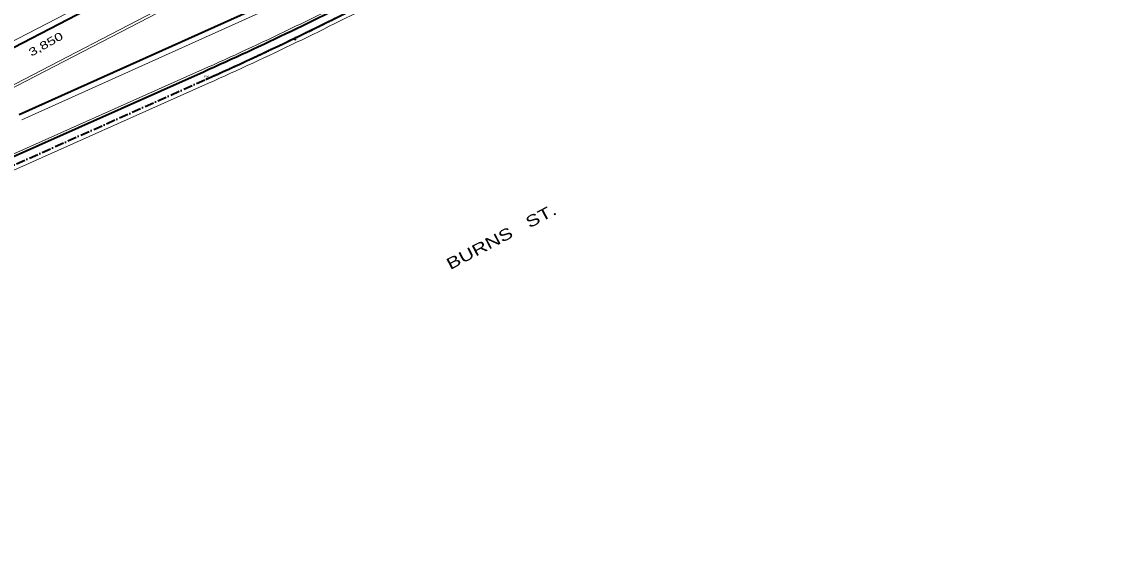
# Model space of a CAD drawing. Extents: x 2354993 to 2372084, y 6966390 to 6990057.
# Drawn here: x 2359644 to 2361546, y 6975784 to 6976700 of the extents above; entities that cross this region are included whole.
import ezdxf
from ezdxf.enums import TextEntityAlignment as Align

# ---------------------------------------------------------------- set-up
doc = ezdxf.new("R2010")
doc.units = 0
doc.header["$LTSCALE"] = 3.2
doc.linetypes.add('DOT_DASHED', pattern=[7.7, 5, -1.2, 0.3, -1.2])
for name, color, linetype, lineweight in [('1', 7, 'Continuous', 13), ('13', 7, 'Continuous', 13), ('2', 7, 'Continuous', 35), ('5', 7, 'Continuous', 35), ('6', 7, 'Continuous', 35)]:
    doc.layers.add(name, color=color, linetype=linetype, lineweight=lineweight)

msp = doc.modelspace()

# ---------------------------------------------------------------- linework, layer by layer
at = {"layer": '1'}
for p, q in [((2360123.835, 6976669.105), (2360120.335, 6976669.105)), ((2360123.835, 6976669.105), (2360120.335, 6976669.105)), ((2360122.085, 6976670.855), (2360122.085, 6976667.355)), ((2360122.085, 6976670.855), (2360122.085, 6976667.355)), ((2359968.831, 6976599.907), (2359965.331, 6976599.907)), ((2359968.833, 6976599.908), (2359965.333, 6976599.908)), ((2359967.081, 6976601.657), (2359967.081, 6976598.157)), ((2359967.083, 6976601.658), (2359967.083, 6976598.158))]:
    msp.add_line(p, q, dxfattribs=at)
at = {"layer": '1', "lineweight": 35}
msp.add_arc((2357631.41, 6981831.8), 5729.578, 294.05742, 297.45135, dxfattribs=at)
at = {"layer": '5', "lineweight": 13}
for p, q in [((2358077.838, 6975783.754), (2361546.398, 6977586.361)), ((2359530.419, 6976533.69), (2360298.445, 6976932.155)), ((2359643.558, 6976528.673), (2360539.614, 6976932.098)), ((2358933.627, 6976305.141), (2359820.865, 6976766.238))]:
    msp.add_line(p, q, dxfattribs=at)
at = {"layer": '5'}
for p, q in [((2359639.244, 6976537.697), (2360535.509, 6976941.217)), ((2358938.418, 6976296.361), (2359825.476, 6976757.364))]:
    msp.add_line(p, q, dxfattribs=at)
at = {"layer": '6', "lineweight": 13}
for p, q in [((2358997.069, 6976186.577), (2359959.749, 6976616.346)), ((2359007.668, 6976162.836), (2359970.348, 6976592.605))]:
    msp.add_line(p, q, dxfattribs=at)
at = {"layer": '6'}
msp.add_line((2358998.699, 6976182.924), (2359961.379, 6976612.693), dxfattribs=at)
at = {"layer": '6', "linetype": 'DOT_DASHED'}
msp.add_line((2359004.406, 6976170.14), (2359967.083, 6976599.908), dxfattribs=at)
msp.add_line((2359004.406, 6976170.14), (2359967.083, 6976599.908), dxfattribs=at)
at = {"layer": '6', "lineweight": 13}
for radius in [5711.578, 5737.578]:
    msp.add_arc((2357631.414, 6981831.802), radius, 294.05739, 297.45137, dxfattribs=at)
at = {"layer": '6'}
msp.add_arc((2357631.414, 6981831.802), 5715.578, 294.05739, 297.45137, dxfattribs=at)
at = {"layer": '6', "linetype": 'DOT_DASHED'}
for centre, start in [((2357631.409, 6981831.799), 294.05741), ((2357631.41, 6981831.8), 294.05742), ((2357631.41, 6981831.8), 294.05742)]:
    msp.add_arc(centre, 5729.578, start, 297.45135, dxfattribs=at)

# ---------------------------------------------------------------- texts
at = {"layer": '13', "width": 1.4}
msp.add_text('3,850', height=14, rotation=29.183, dxfattribs=at).set_placement((2359660.404, 6976638.94))
at = {"layer": '13', "width": 1.35}
msp.add_text('BURNS   ST.', height=20, rotation=27.748, dxfattribs=at).set_placement((2360487.439, 6976314.955), align=Align.CENTER)
at = {"layer": '2'}
for s, width, p in [('F33', 1.15, (2360117.497, 6976671.305)), ('F26', 1.1, (2359962.575, 6976602.107))]:
    msp.add_text(s, height=3.5, dxfattribs=dict(at, width=width)).set_placement(p)

doc.saveas('drawing.dxf')
